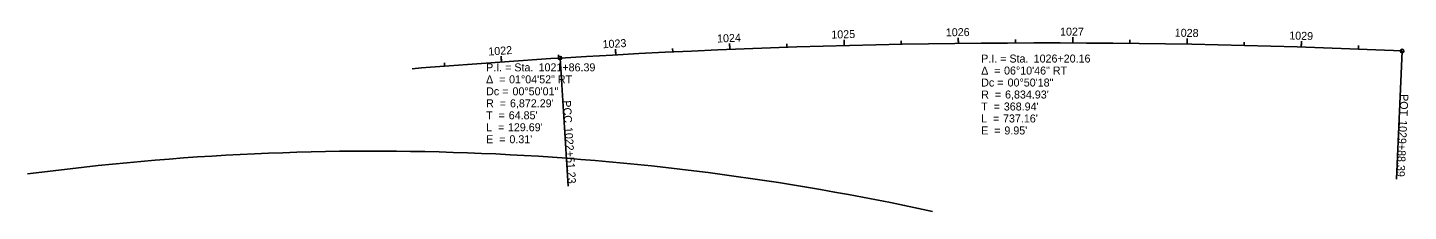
# Model space of a CAD drawing. Extents: x 2189048 to 2198002, y 659562 to 661773.
# Drawn here: x 2196794 to 2198002, y 661612 to 661773 of the extents above; entities that cross this region are included whole.
import ezdxf

# ---------------------------------------------------------------- set-up
doc = ezdxf.new("R2010")
doc.units = 0
for name, color, linetype in [('GE_X_Alignment', 7, 'Continuous'), ('GE_X_Alignment_1000_Curve_Data', 7, 'Continuous'), ('GE_X_Alignment_1000_Stations', 7, 'Continuous'), ('GE_X_Alignment_100_Curve_Data', 7, 'Continuous'), ('GE_X_Alignment_100_Stations', 7, 'Continuous'), ('GE_X_Alignment_500_Curve_Data', 7, 'Continuous'), ('GE_X_Alignment_500_Stations', 7, 'Continuous'), ('SC_Scratch2', 7, 'Continuous')]:
    doc.layers.add(name, color=color, linetype=linetype)

msp = doc.modelspace()

# ---------------------------------------------------------------- linework, layer by layer
at = {"layer": 'GE_X_Alignment'}
for centre, radius, start, end in [((2197685.6, 654925), 6834.9, 87.39548, 93.57492), ((2197687.9, 654887.7), 6872.3, 93.57492, 94.65616)]:
    msp.add_arc(centre, radius, start, end, dxfattribs=at)
at = {"layer": 'GE_X_Alignment_1000_Stations'}
for p, q in [((2197507.9, 661757.6), (2197507.8, 661760.6)), ((2197259.4, 661746.6), (2197266.4, 661634.3)), ((2197996.1, 661752.8), (2197991, 661640.5))]:
    msp.add_line(p, q, dxfattribs=at)
for centre in [(2197259.4, 661746.6), (2197996.1, 661752.8)]:
    msp.add_circle(centre, 1.5, dxfattribs=at)
at = {"layer": 'GE_X_Alignment_100_Stations'}
for p, q in [((2197407.9, 661754.3), (2197407.7, 661759.3)), ((2197457.9, 661756.1), (2197457.8, 661759.1)), ((2197507.9, 661757.6), (2197507.8, 661762.6)), ((2197557.9, 661758.7), (2197557.8, 661761.7)), ((2197607.9, 661759.5), (2197607.8, 661764.5)), ((2197657.9, 661759.9), (2197657.9, 661762.9)), ((2197707.9, 661759.9), (2197707.9, 661764.9)), ((2197757.9, 661759.5), (2197757.9, 661762.5)), ((2197807.9, 661758.8), (2197808, 661763.8)), ((2197857.9, 661757.7), (2197857.9, 661760.7)), ((2197907.8, 661756.3), (2197908, 661761.3)), ((2197208.3, 661743.2), (2197207.9, 661748.2)), ((2197258.1, 661746.5), (2197258, 661749.5)), ((2197259.4, 661746.6), (2197266.4, 661634.3)), ((2197308.1, 661749.5), (2197307.8, 661754.5)), ((2197358, 661752.1), (2197357.9, 661755)), ((2197957.8, 661754.5), (2197957.9, 661757.5)), ((2197996.1, 661752.8), (2197991, 661640.5)), ((2197158.4, 661739.6), (2197158.2, 661742.5))]:
    msp.add_line(p, q, dxfattribs=at)
for centre in [(2197259.4, 661746.6), (2197996.1, 661752.8)]:
    msp.add_circle(centre, 1.5, dxfattribs=at)
at = {"layer": 'GE_X_Alignment_500_Stations'}
for p, q in [((2197507.9, 661757.6), (2197507.8, 661762.6)), ((2197607.9, 661759.5), (2197607.8, 661762.5)), ((2197707.9, 661759.9), (2197707.9, 661762.9)), ((2197807.9, 661758.8), (2197807.9, 661761.8)), ((2197907.8, 661756.3), (2197907.9, 661759.3)), ((2197259.4, 661746.6), (2197266.4, 661634.3)), ((2197308.1, 661749.5), (2197307.9, 661752.5)), ((2197407.9, 661754.3), (2197407.8, 661757.3)), ((2197996.1, 661752.8), (2197991, 661640.5)), ((2197208.3, 661743.2), (2197208, 661746.2))]:
    msp.add_line(p, q, dxfattribs=at)
for centre in [(2197259.4, 661746.6), (2197996.1, 661752.8)]:
    msp.add_circle(centre, 1.5, dxfattribs=at)
at = {"layer": 'SC_Scratch2'}
msp.add_arc((2197095.9, 659373.3), 2291.8, 77.6734, 97.5794, dxfattribs=at)

# ---------------------------------------------------------------- texts
at = {"layer": 'GE_X_Alignment_1000_Curve_Data'}
for s, p in [('P.I. = Sta. ', (2197627.8, 661742.7)), ('1026+20.16', (2197673.7, 661742.7)), ('P.I. = Sta. ', (2197194.7, 661735)), ('1021+86.39', (2197240.6, 661735)), ('Δ  = ', (2197627.8, 661732.2)), ('06°10\'46" RT', (2197647.8, 661732.2)), ('Δ  = ', (2197194.7, 661724.5)), ('01°04\'52" RT', (2197214.8, 661724.5)), ('Dc = ', (2197627.8, 661721.7)), ('00°50\'18"', (2197650.9, 661721.7)), ('Dc = ', (2197194.7, 661714)), ('R  = ', (2197194.7, 661703.5)), ("6,872.29'", (2197215.6, 661703.5)), ('00°50\'01"', (2197217.8, 661714)), ('R  = ', (2197627.8, 661711.2)), ("6,834.93'", (2197648.7, 661711.2)), ('T  = ', (2197194.7, 661693)), ("64.85'", (2197214.5, 661693)), ('T  = ', (2197627.8, 661700.7)), ("368.94'", (2197647.6, 661700.7)), ('L  = ', (2197194.7, 661682.5)), ("129.69'", (2197213.8, 661682.5)), ('L  = ', (2197627.8, 661690.2)), ('E  = ', (2197627.8, 661679.7)), ("737.16'", (2197646.9, 661690.2)), ("9.95'", (2197648.1, 661679.7)), ('E  = ', (2197194.7, 661672)), ("0.31'", (2197215.1, 661672))]:
    msp.add_text(s, height=7, dxfattribs=at).set_placement(p)
at = {"layer": 'GE_X_Alignment_1000_Stations'}
for s, rotation, p in [('POT', 267.3955, (2197994.6, 661715.2)), ('PCC', 273.5749, (2197261.8, 661709.3)), ('1029+88.39', 267.3955, (2197993.5, 661692.4)), ('1022+51.23', 273.5749, (2197263.3, 661686))]:
    msp.add_text(s, height=7, rotation=rotation, dxfattribs=at).set_placement(p)
at = {"layer": 'GE_X_Alignment_100_Curve_Data'}
for s, p in [('P.I. = Sta. ', (2197627.8, 661742.7)), ('1026+20.16', (2197673.7, 661742.7)), ('P.I. = Sta. ', (2197194.7, 661735)), ('1021+86.39', (2197240.6, 661735)), ('Δ  = ', (2197627.8, 661732.2)), ('06°10\'46" RT', (2197647.8, 661732.2)), ('Δ  = ', (2197194.7, 661724.5)), ('01°04\'52" RT', (2197214.8, 661724.5)), ('Dc = ', (2197627.8, 661721.7)), ('00°50\'18"', (2197650.9, 661721.7)), ('Dc = ', (2197194.7, 661714)), ('R  = ', (2197194.7, 661703.5)), ("6,872.29'", (2197215.6, 661703.5)), ('00°50\'01"', (2197217.8, 661714)), ('R  = ', (2197627.8, 661711.2)), ("6,834.93'", (2197648.7, 661711.2)), ('T  = ', (2197194.7, 661693)), ("64.85'", (2197214.5, 661693)), ('T  = ', (2197627.8, 661700.7)), ("368.94'", (2197647.6, 661700.7)), ('L  = ', (2197194.7, 661682.5)), ("129.69'", (2197213.8, 661682.5)), ('L  = ', (2197627.8, 661690.2)), ('E  = ', (2197627.8, 661679.7)), ("737.16'", (2197646.9, 661690.2)), ("9.95'", (2197648.1, 661679.7)), ('E  = ', (2197194.7, 661672)), ("0.31'", (2197215.1, 661672))]:
    msp.add_text(s, height=7, dxfattribs=at).set_placement(p)
at = {"layer": 'GE_X_Alignment_100_Stations'}
for s, rotation, p in [('1025', 1.4895, (2197496.8, 661763.7)), ('1026', 0.6512, (2197596.9, 661765.7)), ('1027', 359.813, (2197696.8, 661766.3)), ('1028', 358.9747, (2197797.1, 661765.4)), ('1023', 3.1661, (2197296.8, 661755.2)), ('1024', 2.3278, (2197396.9, 661760.2)), ('1029', 358.1364, (2197897.2, 661763)), ('1022', 4.002, (2197196.9, 661748.8)), ('POT', 267.3955, (2197994.6, 661715.2)), ('PCC', 273.5749, (2197261.8, 661709.3)), ('1029+88.39', 267.3955, (2197993.5, 661692.4)), ('1022+51.23', 273.5749, (2197263.3, 661686))]:
    msp.add_text(s, height=7, rotation=rotation, dxfattribs=at).set_placement(p)
at = {"layer": 'GE_X_Alignment_500_Curve_Data'}
for s, p in [('P.I. = Sta. ', (2197627.8, 661742.7)), ('1026+20.16', (2197673.7, 661742.7)), ('P.I. = Sta. ', (2197194.7, 661735)), ('1021+86.39', (2197240.6, 661735)), ('Δ  = ', (2197627.8, 661732.2)), ('06°10\'46" RT', (2197647.8, 661732.2)), ('Δ  = ', (2197194.7, 661724.5)), ('01°04\'52" RT', (2197214.8, 661724.5)), ('Dc = ', (2197627.8, 661721.7)), ('00°50\'18"', (2197650.9, 661721.7)), ('Dc = ', (2197194.7, 661714)), ('R  = ', (2197194.7, 661703.5)), ("6,872.29'", (2197215.6, 661703.5)), ('00°50\'01"', (2197217.8, 661714)), ('R  = ', (2197627.8, 661711.2)), ("6,834.93'", (2197648.7, 661711.2)), ('T  = ', (2197194.7, 661693)), ("64.85'", (2197214.5, 661693)), ('T  = ', (2197627.8, 661700.7)), ("368.94'", (2197647.6, 661700.7)), ('L  = ', (2197194.7, 661682.5)), ("129.69'", (2197213.8, 661682.5)), ('L  = ', (2197627.8, 661690.2)), ('E  = ', (2197627.8, 661679.7)), ("737.16'", (2197646.9, 661690.2)), ("9.95'", (2197648.1, 661679.7)), ('E  = ', (2197194.7, 661672)), ("0.31'", (2197215.1, 661672))]:
    msp.add_text(s, height=7, dxfattribs=at).set_placement(p)
at = {"layer": 'GE_X_Alignment_500_Stations'}
for s, rotation, p in [('1025', 1.4895, (2197496.8, 661763.7)), ('POT', 267.3955, (2197994.6, 661715.2)), ('PCC', 273.5749, (2197261.8, 661709.3)), ('1029+88.39', 267.3955, (2197993.5, 661692.4)), ('1022+51.23', 273.5749, (2197263.3, 661686))]:
    msp.add_text(s, height=7, rotation=rotation, dxfattribs=at).set_placement(p)

doc.saveas('drawing.dxf')
